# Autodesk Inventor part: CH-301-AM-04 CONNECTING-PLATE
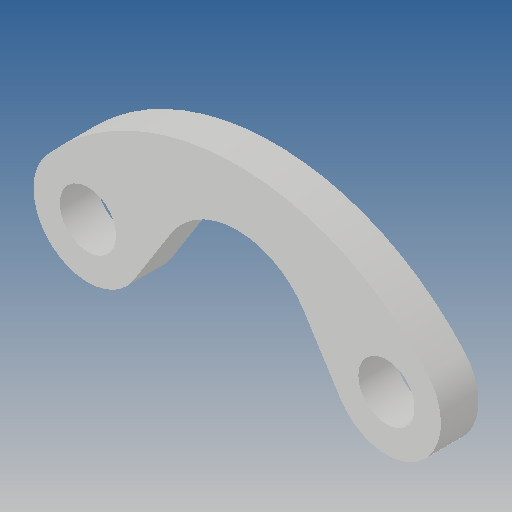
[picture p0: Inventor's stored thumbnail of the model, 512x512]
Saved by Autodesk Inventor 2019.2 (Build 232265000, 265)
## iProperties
Created: 2012-09
Part Number: CH-301-AM-04 CONNECTING-PLATE
Material: Ogólny
Document SubType Name: Modeling
Designer: CADENGINEERING4
Density: 1 g/cm^3
Appearance: Domyślna
Author: CADENGINEERING4
Revision Number: ÈÎºÎ
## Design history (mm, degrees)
feature "À­Éì1"
node "Bryła1"
